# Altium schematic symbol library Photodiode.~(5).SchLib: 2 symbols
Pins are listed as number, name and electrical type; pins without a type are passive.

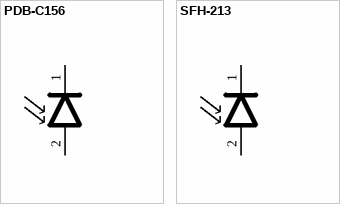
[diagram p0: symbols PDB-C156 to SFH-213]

## PDB-C156
designator PD?  Supplier Part Number 1: PDB-C156-ND
Photodiode; Manufacturer: Used in BOM report; SymbolVersion: use current date i.e. 2008-05-20; SymbolCreator: Use LDAP id; CompType: Used in some BOM reports.  Useful for finding later.; U/M: EA, IN, or GM
footprint PDB-C156 (Photodiode)
pins: 1 C, 2 A

## SFH-213
designator PD?, comment SFH213
Manufacturer: Osram; SymbolVersion: use current date i.e. 2008-05-20; SymbolCreator: Use LDAP id; CompType: Used in some BOM reports.  Useful for finding later.; U/M: EA, IN, or GM
footprint PDB-C156 (Photodiode)
pins: 1 C, 2 A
